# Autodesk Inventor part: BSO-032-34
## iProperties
Author: Administrator
Shininess: 25.0
Angle Display Precision: 2
Document Length Units: 11272
Document Angle Units: 11286
Document Time Units: 11279
Document Mass Units: 11290
Document Length Units Precision: 3
Document Angle Units Precision: 2
Compacted: True
PropertySet Name: _Private Model Information
Created: 2001-09
Part Number: BSO-032-34
Material: Steel, High Strength Low Alloy
Description: PEM, Blind Standoff, BSO-10-32 UNFx34
Document SubType Name: Modeling
Designer: Administrator
Control State: 0
Master: False
Checked Out: False
PropertySet Name: Design Tracking Control
Density: 7.84
Volumn: 0.17245559573138858
Area: 3.4800931280430336
PropertySet Name: Model Information
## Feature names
1. Extrusion1
2. Extrusion2
3. Revolution1
4. Revolution2
5. Rectangular Pattern1
6. Hole1
7. Chamfer3
8. Chamfer4
